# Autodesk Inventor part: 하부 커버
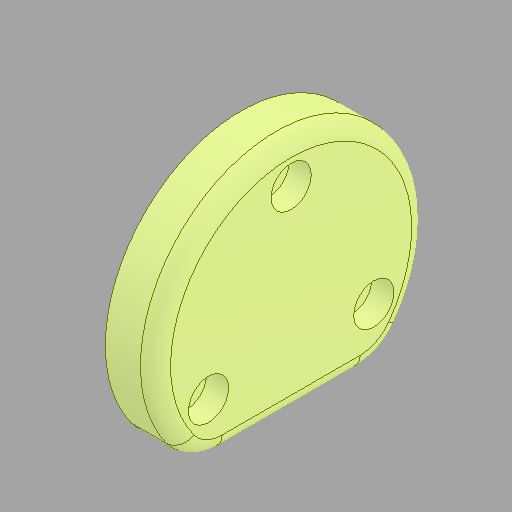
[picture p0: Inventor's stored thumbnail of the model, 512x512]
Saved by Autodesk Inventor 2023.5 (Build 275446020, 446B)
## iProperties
Created: 2026-03
Part Number: 하부 커버
Material: 알루미늄 6061
Document SubType Name: Modeling
Designer: mirae
Density: 2.7 g/cm^3
Appearance: 기본값
Author: jhkim
Sending System: Autodesk Inventor 2026
Preprocessor: ST-DEVELOPER v20.1
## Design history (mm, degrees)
node "하부 커버1"
node "솔리드2"
node "솔리드1"
